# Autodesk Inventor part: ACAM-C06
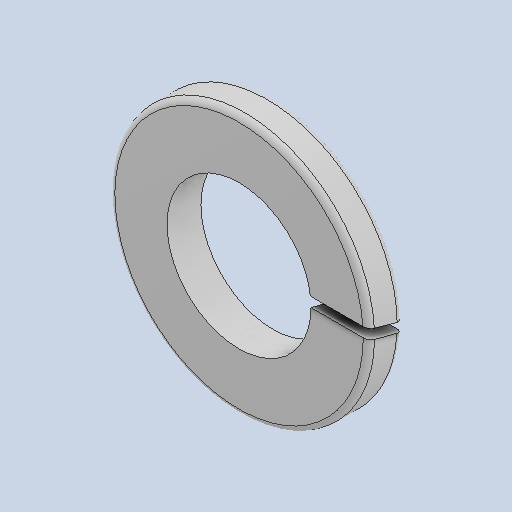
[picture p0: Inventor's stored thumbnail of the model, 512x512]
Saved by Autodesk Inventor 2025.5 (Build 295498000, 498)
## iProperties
Created: 2026-10
Part Number: ACAM-C06
Material: Genérico
Document SubType Name: Modeling
Designer: Luis M
Density: 1 g/cm^3
Appearance: Valor por defecto
Description: Arandela de presión M5 — DIN 127 B
Sending System: SolidEdge
MC: COSTA-PC
OS: Windows NT
OS_RELEASE: 6.1
FRU: Unigraphics Solutions
SITE: Huntsville, AL
FORMAT: text
GUISE: transmit
KEY: D:\Videos_Canal\GrabCAD\Arruela de pressao DIN 127 B\Arruela de pressao DIN 127 B - M5
FILE: D:\Videos_Canal\GrabCAD\Arruela de pressao DIN 127 B\Arruela de pressao DIN 127 B - M5.x_t
DATE: ter, abr 05 16
Material_BOM: Por especificar
Proceso_BOM: Comercial
Author: Luis M
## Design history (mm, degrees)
feature "Base1"
node "Sólido1"
